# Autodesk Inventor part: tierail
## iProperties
Created: 2005-05
Part Number: tierail
Material: cherry
Document SubType Name: Modeling
Designer: a.campbell
Manufacturer: Standard
Standards Organization: Custom
length: 338
thickness: 19
width: 45
Author: a.campbell
Comments: machine to detail
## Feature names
1. Extrusion1
